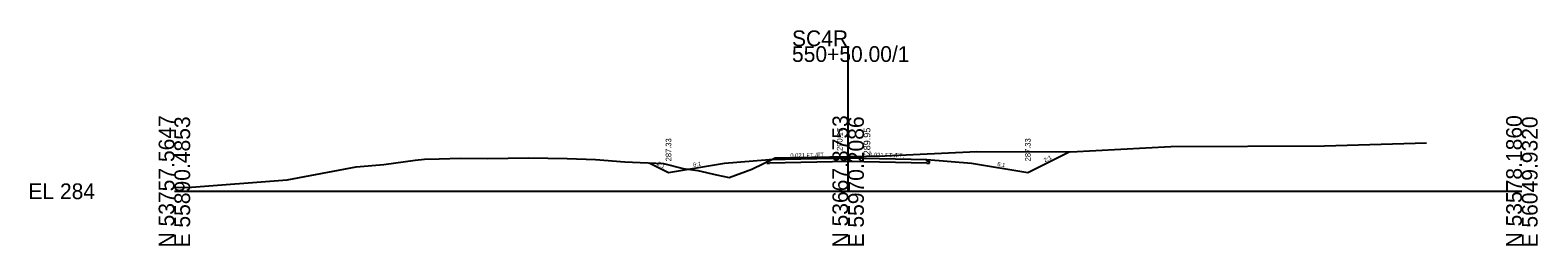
# Model space of a CAD drawing. Extents: x 9740 to 17409, y 8856 to 28416.
# Drawn here: x 12740.2 to 13008.7, y 11361.7 to 11400 of the extents above; entities that cross this region are included whole.
import ezdxf

# ---------------------------------------------------------------- set-up
doc = ezdxf.new("R2010")
doc.units = 0
for name, color, linetype in [('Level 10', 7, 'Continuous'), ('Level 11', 7, 'Continuous'), ('Level 12', 7, 'Continuous'), ('Level 32', 7, 'Continuous'), ('Level 33', 7, 'Continuous'), ('Level 59', 7, 'Continuous'), ('Level 6', 7, 'Continuous'), ('Level 60', 7, 'Continuous'), ('Level 63', 7, 'Continuous'), ('Level 7', 7, 'Continuous')]:
    doc.layers.add(name, color=color, linetype=linetype)

msp = doc.modelspace()

# ---------------------------------------------------------------- linework, layer by layer
at = {"layer": 'Level 11'}
for p, q in [((12871.85, 11376.74), (12871.35, 11376.73)), ((12871.35, 11376.73), (12871.35, 11376.39)), ((12871.35, 11376.39), (12871.85, 11376.4)), ((12871.85, 11377.04), (12871.85, 11376.74)), ((12899.85, 11376.74), (12899.85, 11377.04)), ((12900.35, 11376.73), (12899.85, 11376.74)), ((12899.85, 11376.4), (12900.35, 11376.39)), ((12900.35, 11376.39), (12900.35, 11376.73))]:
    msp.add_line(p, q, dxfattribs=at)
at = {"layer": 'Level 12'}
for p, q in [((12885.85, 11376.69), (12871.85, 11376.4)), ((12899.85, 11376.4), (12885.85, 11376.69))]:
    msp.add_line(p, q, dxfattribs=at)
at = {"layer": 'Level 59'}
for p, q in [((12871.85, 11377.04), (12885.85, 11377.33)), ((12885.85, 11377.33), (12899.85, 11377.04))]:
    msp.add_line(p, q, dxfattribs=at)
at = {"layer": 'Level 6'}
for p, q in [((12863.85, 11376.37), (12871.85, 11377.04)), ((12899.85, 11377.04), (12907.85, 11376.37))]:
    msp.add_line(p, q, dxfattribs=at)
at = {"layer": 'Level 60'}
for p, q in [((12892.39, 11377.67), (12908.79, 11378.43)), ((12908.79, 11378.43), (12925.53, 11378.39)), ((12925.53, 11378.39), (12943.33, 11379.35)), ((12943.33, 11379.35), (12970.69, 11379.44)), ((12970.69, 11379.44), (12988.86, 11379.98)), ((12785.96, 11373.44), (12798.22, 11375.71)), ((12798.22, 11375.71), (12803.18, 11376.16)), ((12803.18, 11376.16), (12808.73, 11376.92)), ((12808.73, 11376.92), (12810.42, 11377.09)), ((12810.42, 11377.09), (12813.01, 11377.17)), ((12813.01, 11377.17), (12816.79, 11377.24)), ((12816.79, 11377.24), (12821.67, 11377.2)), ((12821.67, 11377.2), (12828.94, 11377.32)), ((12828.94, 11377.32), (12835.79, 11377.23)), ((12835.79, 11377.23), (12840.85, 11377.01)), ((12840.85, 11377.01), (12846.08, 11376.62)), ((12846.08, 11376.62), (12852.97, 11376.32)), ((12852.97, 11376.32), (12856.46, 11375.43)), ((12856.46, 11375.43), (12859.1, 11375.06)), ((12864.68, 11373.81), (12868.71, 11375.33)), ((12868.71, 11375.33), (12872.88, 11377.32)), ((12872.88, 11377.32), (12885.85, 11377.55)), ((12885.85, 11377.55), (12892.39, 11377.67)), ((12768.1, 11372.04), (12785.96, 11373.44)), ((12859.1, 11375.06), (12862.39, 11374.31)), ((12862.39, 11374.31), (12864.68, 11373.81)), ((12765.85, 11372.12), (12768.1, 11372.04))]:
    msp.add_line(p, q, dxfattribs=at)
at = {"layer": 'Level 63'}
for p, q in [((12885.85, 11371.38), (12885.85, 11397.18)), ((12765.85, 11371.38), (12885.85, 11371.38)), ((12885.85, 11371.38), (13005.85, 11371.38))]:
    msp.add_line(p, q, dxfattribs=at)
at = {"layer": 'Level 7'}
for p, q in [((12917.85, 11374.71), (12925.21, 11378.39)), ((12850.4, 11376.43), (12853.85, 11374.71)), ((12853.85, 11374.71), (12863.85, 11376.37)), ((12907.85, 11376.37), (12917.85, 11374.71))]:
    msp.add_line(p, q, dxfattribs=at)

# ---------------------------------------------------------------- texts
at = {"layer": 'Level 10'}
msp.add_text('290.17', height=1, rotation=90, dxfattribs=at).set_placement((12884.85, 11378.55))
at = {"layer": 'Level 32'}
for s, rotation, p in [('0.021 FT./FT.', 1.1916, (12875.56, 11377.37)), ('0.021 FT./FT.', 358.8084, (12889.57, 11377.51)), ('2:1', 333.435, (12851.73, 11376.05)), ('6:1', 9.4623, (12858.29, 11375.7)), ('6:1', 350.5377, (12912.37, 11375.88)), ('2:1', 26.5651, (12920.91, 11376.52))]:
    msp.add_text(s, height=0.75, rotation=rotation, dxfattribs=at).set_placement(p)
at = {"layer": 'Level 33'}
for p in [(12854.35, 11376.71), (12918.35, 11376.71)]:
    msp.add_text('287.33', height=1, rotation=90, dxfattribs=at).set_placement(p)
at = {"layer": 'Level 59'}
msp.add_text(' 289.95', height=1.2, rotation=90, dxfattribs=at).set_placement((12889.81, 11377.33))
at = {"layer": 'Level 63'}
for s, p in [('SC4R', (12875.85, 11397.18)), ('550+50.00/1', (12875.85, 11394.38)), ('EL 284', (12739.85, 11369.98))]:
    msp.add_text(s, height=2.8, dxfattribs=at).set_placement(p)
for s, p in [('N 53757.5647', (12765.85, 11361.38)), ('E 55890.4853', (12768.65, 11361.38)), ('N 53667.8753', (12885.85, 11361.38)), ('E 55970.2086', (12888.65, 11361.38)), ('N 53578.1860', (13005.85, 11361.38)), ('E 56049.9320', (13008.65, 11361.38))]:
    msp.add_text(s, height=2.8, rotation=90, dxfattribs=at).set_placement(p)

doc.saveas('drawing.dxf')
